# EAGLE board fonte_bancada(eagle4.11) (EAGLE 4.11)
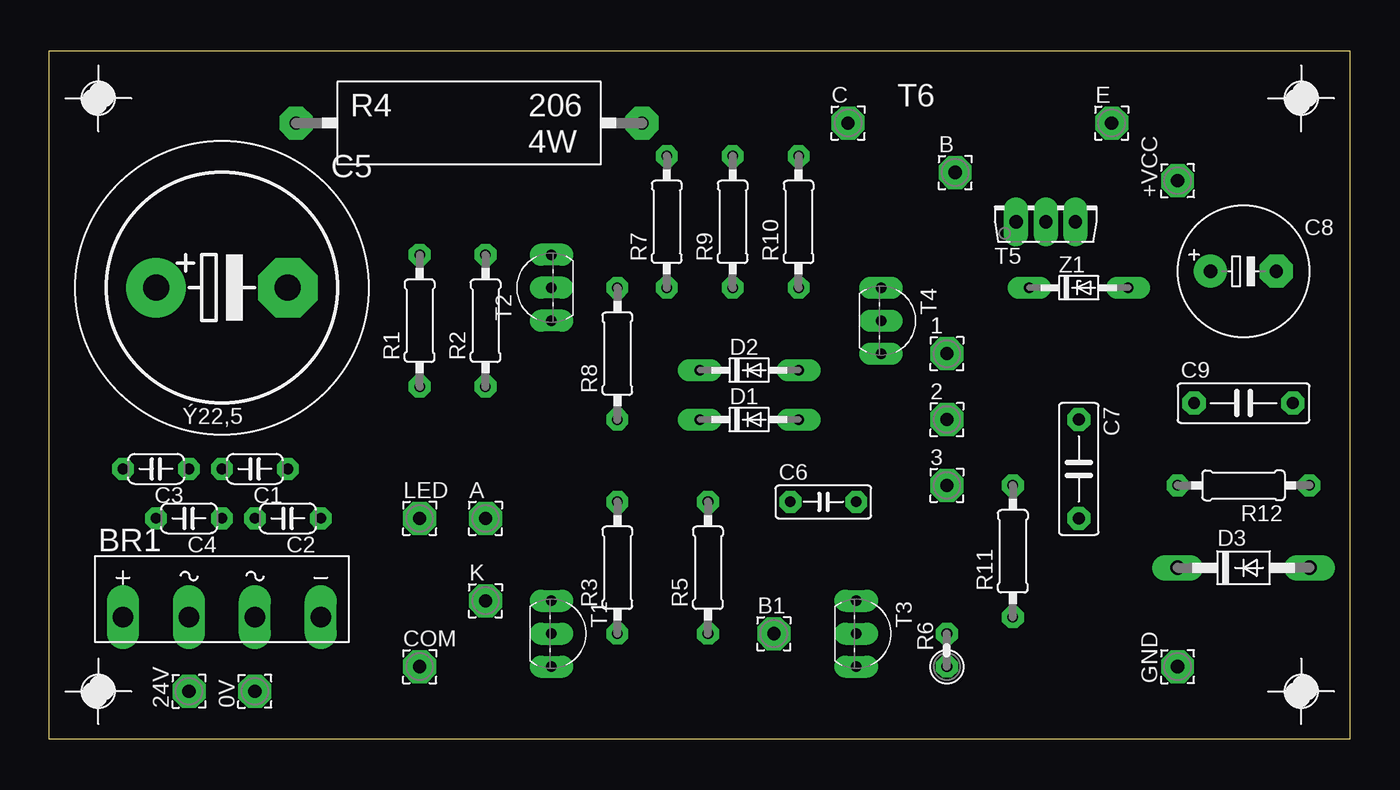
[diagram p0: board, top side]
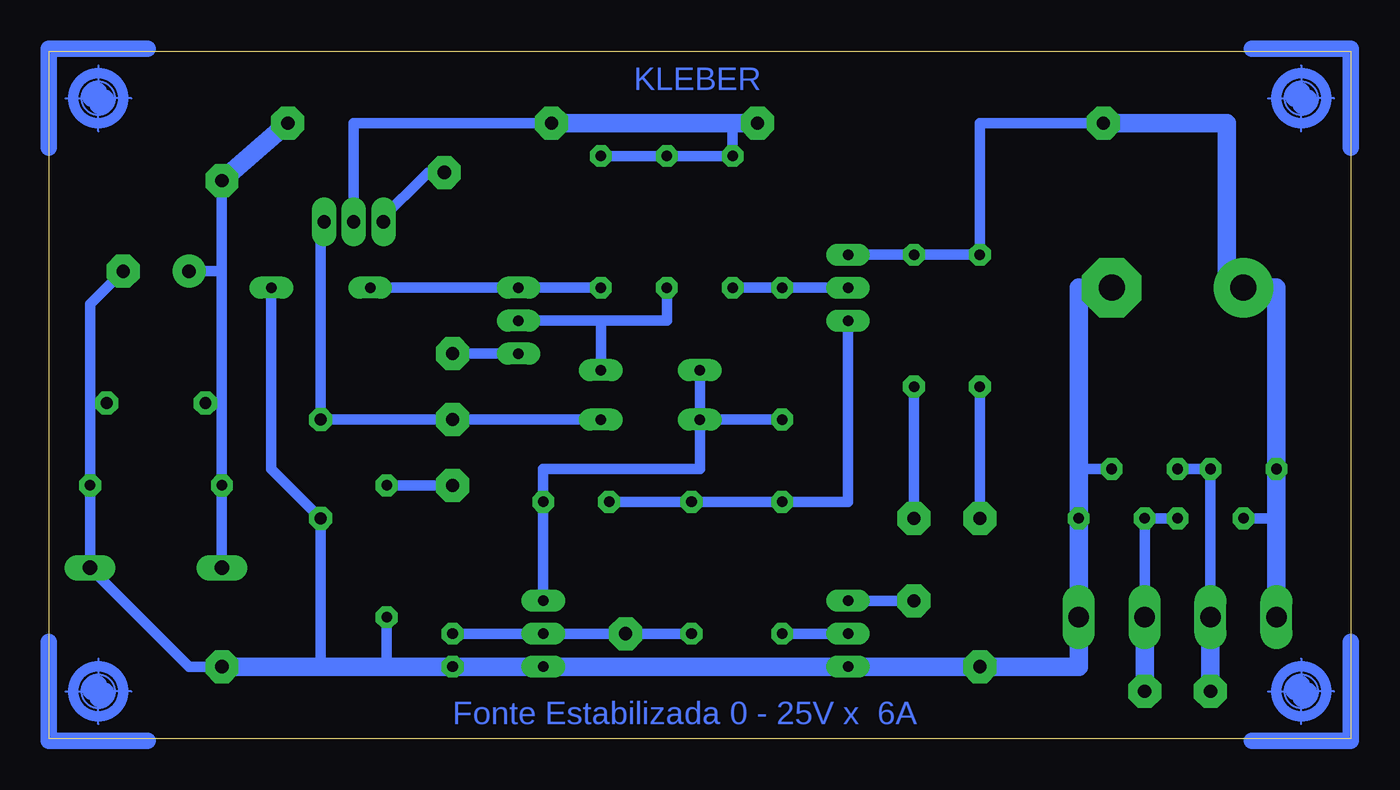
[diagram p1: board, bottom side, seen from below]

Size 100.31 x 53.01 mm. Coordinates in mm from the lower left corner, seen from the top.
Outline: 0,0 100.31,0 100.31,53.01 0,53.01 0,0
Copper layers (1*16): Top 0.035mm / dielectric 1.5mm / Bottom 0.035mm
Design rules "default": minimum track width 32mil, minimum drill 24mil, track to track 18mil, track to pad 18mil, pad to pad 18mil, via to via 18mil, smd to smd 8mil, copper to edge 40mil, drill to drill 18mil, minimum pad ring 17mil, minimum via ring 8mil, stop-mask expansion 4mil, vias tented up to drill 0mil, thermal gap 10mil

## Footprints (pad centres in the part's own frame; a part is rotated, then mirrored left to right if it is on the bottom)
2,54/1,0 = drill 1.016 pad 2.54 octagon: 1 0,0
KBL = drill 1.6 long: + -7.62,-1.27; - 7.62,-1.27; AC1 2.54,-1.27; AC2 -2.54,-1.27
C050-024X044 = drill 0.813 octagon: 1 -2.54,0; 2 2.54,0
EB22,5D = drill 2.007 pad 4.597 round: + -5.08,0 | drill 2.007 pad 4.597 octagon: - 5.08,0
C050-025X075 = drill 0.813 octagon: 1 -2.54,0; 2 2.54,0
C075-032X103 = drill 0.914 octagon: 1 -3.81,0; 2 3.81,0
E5-10,5 = drill 1.016 pad 2.54 round: + -2.54,0 | drill 1.016 pad 2.54 octagon: - 2.54,0
DO34-7 = drill 0.813 long: A 3.81,0; C -3.81,0
DO41-10 = drill 1.118 long: A 5.08,0; C -5.08,0
0207/10 = drill 0.813 octagon: 1 -5.08,0; 2 5.08,0
KH206-8 = drill 1.016 pad 2.54 octagon: 1 -13.335,0; 2 13.335,0
0207/2V = drill 0.813 octagon: 1 -1.27,0; 2 1.27,0
TO92-EBC = drill 0.813 long: B 0,-1.27; C -2.54,-1.27; E 2.54,-1.27
TO126AV = drill 1.016 long: B 2.286,-1.27; C 0,-1.27; E -2.286,-1.27
DO34Z7 = drill 0.813 long: A 3.81,0; C -3.81,0

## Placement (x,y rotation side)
0V  [2,54/1,0]  15.87,3.65 90 top
1  [2,54/1,0]  69.21,29.68 0 top
2  [2,54/1,0]  69.21,24.6 0 top
3  [2,54/1,0]  69.21,19.52 0 top
24V  [2,54/1,0]  10.79,3.65 90 top
+VCC  [2,54/1,0]  86.99,43.02 90 top
A  [2,54/1,0]  33.65,16.98 0 top
B  [2,54/1,0]  69.84,43.65 0 top
B1  [2,54/1,0]  55.88,8.09 0 top
BR1  [KBL]  13.33,10.63 0 top
C  [2,54/1,0]  61.59,47.46 0 top
C1  100n  [C050-024X044]  15.87,20.79 180 top
C2  100n  [C050-024X044]  18.41,16.98 180 top
C3  100n  [C050-024X044]  8.25,20.79 180 top
C4  100n  [C050-024X044]  10.79,16.98 180 top
C5  4700u  [EB22,5D]  13.33,34.76 0 top
C6  10n  [C050-025X075]  59.68,18.25 0 top
C7  68n  [C075-032X103]  79.37,20.79 270 top
C8  330u  [E5-10,5]  92.07,36.03 0 top
C9  100n  [C075-032X103]  92.07,25.87 0 top
COM  [2,54/1,0]  28.57,5.55 0 top
D1  1N4148  [DO34-7]  53.97,24.6 0 top
D2  1N4148  [DO34-7]  53.97,28.41 0 top
D3  1N4004  [DO41-10]  92.07,13.17 0 top
E  [2,54/1,0]  81.91,47.46 0 top
GND  [2,54/1,0]  86.99,5.55 90 top
K  [2,54/1,0]  33.65,10.63 0 top
LED  [2,54/1,0]  28.57,16.98 0 top
R1  2k2 - 1W  [0207/10]  28.57,32.22 90 top
R2  2k2 - 1W  [0207/10]  33.65,32.22 90 top
R3  10k  [0207/10]  43.81,13.17 90 top
R4  0R1  [KH206-8]  32.38,47.46 0 top
R5  10k  [0207/10]  50.79,13.17 90 top
R6  4k7  [0207/2V]  69.21,6.82 90 top
R7  180R  [0207/10]  47.62,39.84 90 top
R8  4k7  [0207/10]  43.81,29.68 90 top
R9  10k  [0207/10]  52.7,39.84 90 top
R10  390R  [0207/10]  57.78,39.84 90 top
R11  180R  [0207/10]  74.29,14.44 90 top
R12  10k  [0207/10]  92.07,19.52 180 top
T1  BC547  [TO92-EBC]  40,8.09 270 top
T2  BC557  [TO92-EBC]  37.46,34.76 90 top
T3  BC547  [TO92-EBC]  63.49,8.09 270 top
T4  BC547  [TO92-EBC]  65.4,32.22 270 top
T5  BD135  [TO126AV]  76.83,41.11 0 top
U$1  [PASS-ROUND]  3.81,3.65 0 top
U$2  [PASS-ROUND]  3.81,49.37 0 top
U$3  [PASS-ROUND]  96.52,3.65 0 top
U$4  [PASS-ROUND]  96.52,49.37 0 top
U$5  [ANGLE-SW-1]  0.63,0.47 0 top
U$6  [ANGLE-SW-1]  99.69,0.47 90 top
U$7  [ANGLE-SW-1]  99.69,52.54 180 top
U$8  [ANGLE-SW-1]  0.63,52.54 270 top
Z1  15V  [DO34Z7]  79.37,34.76 0 top

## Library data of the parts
0V 1-3 24V +VCC A B B1 C COM E GND K LED = ilhas - pads
BR1 = pontes-retificadoras
C1-C9 R1-R3 R5-R12 = resistores e capacitores
D1-D3 Z1 = diodos
R4 = resistor-potencia
T1 T3 T4 = transistor-npn
T2 = transistor-pnp
T5 = transistor-potencia
U$1-U$8 = marcas-pci

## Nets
N$2: LED.1 R1.1
N$3: 24V.1 BR1.AC2 C1.2 C3.1
N$6: 0V.1 BR1.AC1 C2.2 C4.1
N$7: A.1 R2.1
N$8: K.1 T1.C
N$9: R3.1 T1.B
N$10: B1.1 R5.1 R6.2 T3.B
N$11: C6.1 R3.2 R5.2 T2.C
N$12: C.1 R4.2 R7.2 R9.2 R10.2 T5.C
N$13: R7.1 R8.2 T2.B
N$14: C6.2 D1.C D2.C R8.1 T3.C
N$15: R10.1 T4.C Z1.C
N$16: 3.1 R11.2
N$17: 2.1 C7.1 D1.A T5.B
N$18: B.1 T5.E
N$20: +VCC.1 C8.+ C9.1 D3.C E.1 R12.2
N$22: BR1.+ C3.2 C4.2 C5.+ R1.2 R2.2 R4.1 T2.E
N$23: 1.1 T4.E
N$24: D2.A R9.1 T4.B
N$26: BR1.- C1.1 C2.1 C5.- C7.2 C8.- C9.2 COM.1 D3.A GND.1 R6.1 R11.1 R12.1 T1.E T3.E Z1.A

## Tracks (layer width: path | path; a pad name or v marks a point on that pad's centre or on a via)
N$2
  Bottom 0.813: LED.1 R1.1
N$3
  Bottom 0.813: BR1.AC2 C3.1 C1.2
  Bottom 1.422: 24V.1 BR1.AC2
N$6
  Bottom 0.813: BR1.AC1 C2.2 C4.1
  Bottom 1.422: 0V.1 BR1.AC1
N$7
  Bottom 0.813: A.1 R2.1
N$8
  Bottom 0.813: K.1 T1.C
N$9
  Bottom 0.813: T1.B R3.1
N$10
  Bottom 0.813: R5.1 B1.1 T3.B R6.2
N$11
  Bottom 0.813: T2.C 38.73,18.25 R3.2 R5.2 | 53.97,18.25 R5.2 | R5.2 C6.1
N$12
  Bottom 0.813: R10.2 R9.2 R7.2 47.62,47.46 | T5.C 76.83,47.46 C.1
  Bottom 1.422: R4.2 47.62,47.46 C.1
N$13
  Bottom 0.813: T2.B R8.2 R7.1
N$14
  Bottom 0.813: T3.C C6.2 62.22,20.79 50.16,20.79 D1.C | D1.C D2.C | R8.1 D1.C
N$15
  Bottom 0.813: R10.1 T4.C Z1.C
N$16
  Bottom 0.813: R11.2 3.1
N$17
  Bottom 0.813: D1.A 2.1 C7.1 79.37,39.84 T5.B
N$18
  Bottom 0.813: T5.E 74.93,39.84 71.12,43.65 B.1
N$20
  Bottom 0.813: D3.C R12.2 86.99,25.87 | 86.99,25.87 86.99,36.03 | 86.99,36.03 C8.+ | 86.99,25.87 C9.1 | 86.99,36.03 +VCC.1
  Bottom 1.422: E.1 +VCC.1
N$22
  Bottom 0.813: BR1.+ 5.71,16.98 | 5.71,16.98 C3.2 | 5.71,16.98 C4.2 | R4.1 28.57,47.46 R1.2 R2.2 T2.E
  Bottom 1.422: 5.71,34.76 C5.+ | BR1.+ 5.71,34.76 | 5.71,34.76 9.52,34.76 9.52,47.46 R4.1
N$23
  Bottom 0.813: 1.1 T4.E
N$24
  Bottom 0.813: R9.1 52.7,32.22 57.78,32.22 | 57.78,32.22 T4.B | 57.78,32.22 D2.A
N$26
  Bottom 0.813: BR1.- C2.1 20.95,20.79 C1.1 | R11.1 74.29,5.55 79.37,5.55 C7.2 83.18,20.79 Z1.A | D3.A R12.1 | D3.A R12.1 | D3.A 89.53,5.55 GND.1 | R12.1 97.15,25.87 | 97.15,25.87 97.15,33.49 C8.- | 97.15,25.87 C9.2
  Bottom 1.422: C5.- 20.95,34.76 BR1.- 20.95,5.55 COM.1 T1.E T3.E R6.1 74.29,5.55 GND.1
(copper drawn outside any net)
  shapes: Bottom circle x4

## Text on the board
Bottom: KLEBER | Fonte Estabilizada 0 - 25V x 6A
tNames: T6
